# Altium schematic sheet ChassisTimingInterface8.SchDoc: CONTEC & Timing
size B; Author: M. Pirello; Organization: LIGO Laboratory; Address1: California Institute of Technology; Address2: Massachusetts Institute of Technology; Address3: National Science Foundation; Address4: Australia 2086; DocumentNumber: 10; SheetNumber: 10; SheetTotal: 12; Size: B
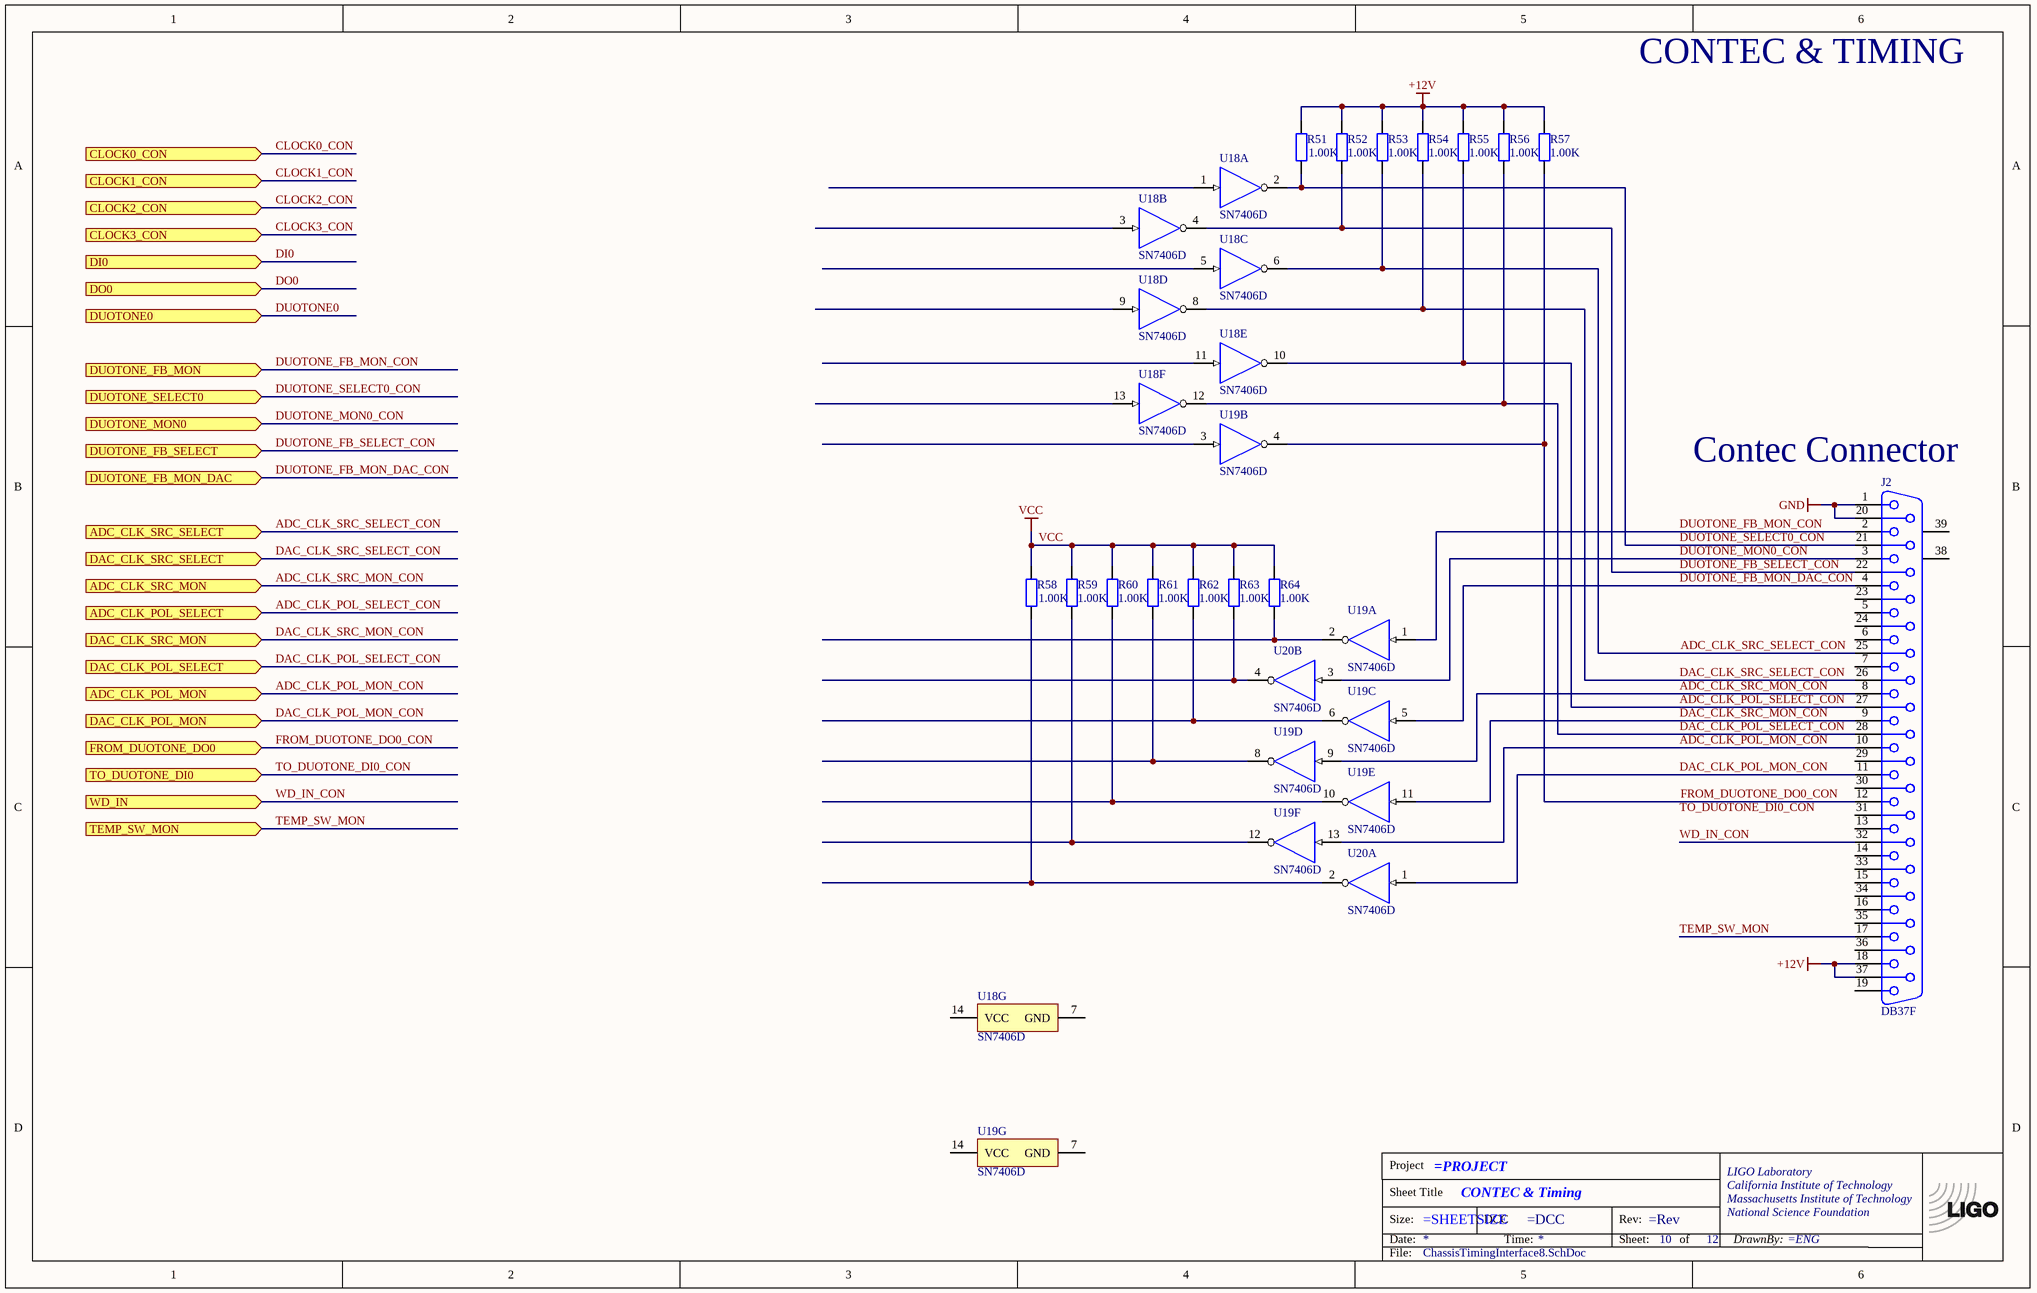
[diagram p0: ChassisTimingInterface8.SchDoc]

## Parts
*?  TitleBlock  (value not drawn)  (graphical)
?  (no value)  (no BOM)
J2  DB37F  [DB37F-RA]
R51  1.00K  [CR1005-0402]
R52  1.00K  [CR1005-0402]
R53  1.00K  [CR1005-0402]
R54  1.00K  [CR1005-0402]
R55  1.00K  [CR1005-0402]
R56  1.00K  [CR1005-0402]
R57  1.00K  [CR1005-0402]
R58  1.00K  [CR1005-0402]
R59  1.00K  [CR1005-0402]
R60  1.00K  [CR1005-0402]
R61  1.00K  [CR1005-0402]
R62  1.00K  [CR1005-0402]
R63  1.00K  [CR1005-0402]
R64  1.00K  [CR1005-0402]
U18  SN7406D  [D0014A_L]  (parts A,B,C,D,E,F,G of 7)
U19  SN7406D  [D0014A_L]  (parts A,B,C,D,E,F,G of 7)
U20  SN7406D  [D0014A_L]  (parts A,B of 7)

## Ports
ADC_CLK_POL_MON (in), ADC_CLK_POL_SELECT (in), ADC_CLK_SRC_MON (in), ADC_CLK_SRC_SELECT (in), CLOCK0_CON (in), CLOCK1_CON (in), CLOCK2_CON (in), CLOCK3_CON (in), DAC_CLK_POL_MON (in), DAC_CLK_POL_SELECT (in), DAC_CLK_SRC_MON (in), DAC_CLK_SRC_SELECT (in), DI0 (in), DO0 (in), DUOTONE0 (in), DUOTONE_FB_MON (in), DUOTONE_FB_MON_DAC (in), DUOTONE_FB_SELECT (in), DUOTONE_MON0 (in), DUOTONE_SELECT0 (in), FROM_DUOTONE_DO0 (in), TEMP_SW_MON (in), TO_DUOTONE_DI0 (in), WD_IN (in)

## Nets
+12V: J2.18 J2.37 R51.2 R52.2 R53.2 R54.2 R55.2 R56.2 R57.2
GND: J2.1 J2.20
VCC: R58.2 R59.2 R60.2 R61.2 R62.2 R63.2 R64.2
ADC_CLK_POL_MON_CON: J2.10 U19.13(6A) ; port ADC_CLK_POL_MON
ADC_CLK_POL_SELECT_CON: J2.27 R55.1 U18.10(~{5Y}) ; port ADC_CLK_POL_SELECT
ADC_CLK_SRC_MON_CON: J2.8 U19.9(4A) ; port ADC_CLK_SRC_MON
ADC_CLK_SRC_SELECT_CON: J2.25 R53.1 U18.6(~{3Y}) ; port ADC_CLK_SRC_SELECT
DAC_CLK_POL_MON_CON: J2.11 U20.1(1A) ; port DAC_CLK_POL_MON
DAC_CLK_POL_SELECT_CON: J2.28 R56.1 U18.12(~{6Y}) ; port DAC_CLK_POL_SELECT
DAC_CLK_SRC_MON_CON: J2.9 U19.11(5A) ; port DAC_CLK_SRC_MON
DAC_CLK_SRC_SELECT_CON: J2.26 R54.1 U18.8(~{4Y}) ; port DAC_CLK_SRC_SELECT
DUOTONE_FB_MON_CON: J2.2 U19.1(1A) ; port DUOTONE_FB_MON
DUOTONE_FB_MON_DAC_CON: J2.4 U19.5(3A) ; port DUOTONE_FB_MON_DAC
DUOTONE_FB_SELECT_CON: J2.22 R52.1 U18.4(~{2Y}) ; port DUOTONE_FB_SELECT
DUOTONE_MON0_CON: J2.3 U20.3(2A) ; port DUOTONE_MON0
DUOTONE_SELECT0_CON: J2.21 R51.1 U18.2(~{1Y}) ; port DUOTONE_SELECT0
FROM_DUOTONE_DO0_CON: J2.12 R57.1 U19.4(~{2Y}) ; port FROM_DUOTONE_DO0
TEMP_SW_MON: J2.17 ; port TEMP_SW_MON
WD_IN_CON: J2.32 ; port WD_IN
NetR58_1: R58.1 U20.2(~{1Y})
NetR59_1: R59.1 U19.12(~{6Y})
NetR60_1: R60.1 U19.10(~{5Y})
NetR61_1: R61.1 U19.8(~{4Y})
NetR62_1: R62.1 U19.6(~{3Y})
NetR63_1: R63.1 U20.4(~{2Y})
NetR64_1: R64.1 U19.2(~{1Y})

Not connected (* = marked no-connect by the designer): J2 5 6 7 13 14 15 16 19 23 24 29 30 31 33 34 35 36 38 39; U18 1(1A) 3(2A) 5(3A) 7(GND) 9(4A) 11(5A) 13(6A) 14(VCC); U19 3(2A) 7(GND) 14(VCC)

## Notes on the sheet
- CONTEC & TIMING
- (near J2) Contec Connector
- Labels drawn without touching a wire or pin: TO_DUOTONE_DI0_CON

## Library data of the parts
? = LIGO_logo: LIGO logo
J2 = DB37F: Receptacle Assembly, 37 Position, Right Angle, .318 Series; Part Number: A32130-ND
R51-R64 = ChipRes1: Resistor, surface mount; Tolerance: 1%
U18-U20 = CMP-1615-00003-3: Hex inverter buffers / drivers with high-voltage outputs, D0014A, TUBE; Manufacturer: Texas Instruments; Generic Part Number: SN7406; Output Type: CMOS; F @ Nom Voltage(Max)(Mhz): 35; Bits(#): 6; Rating: Catalog; tpd @ Nom Voltage(Max)(ns): 23; Schmitt Trigger: No; Voltage(Nom)(V): 5; Input Type: TTL; VCC(Max)(V): 5.25; Output Drive (IOL/IOH)(Max)(mA): 0/40; ICC @ Nom Voltage(Max)(mA): 0.051; VCC(Min)(V): 4.75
